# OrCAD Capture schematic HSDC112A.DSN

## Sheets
1 Block Diagram: title: TUSB216I_217A_EVM; rev: A; company: Texas Instruments; note: HSDC112A
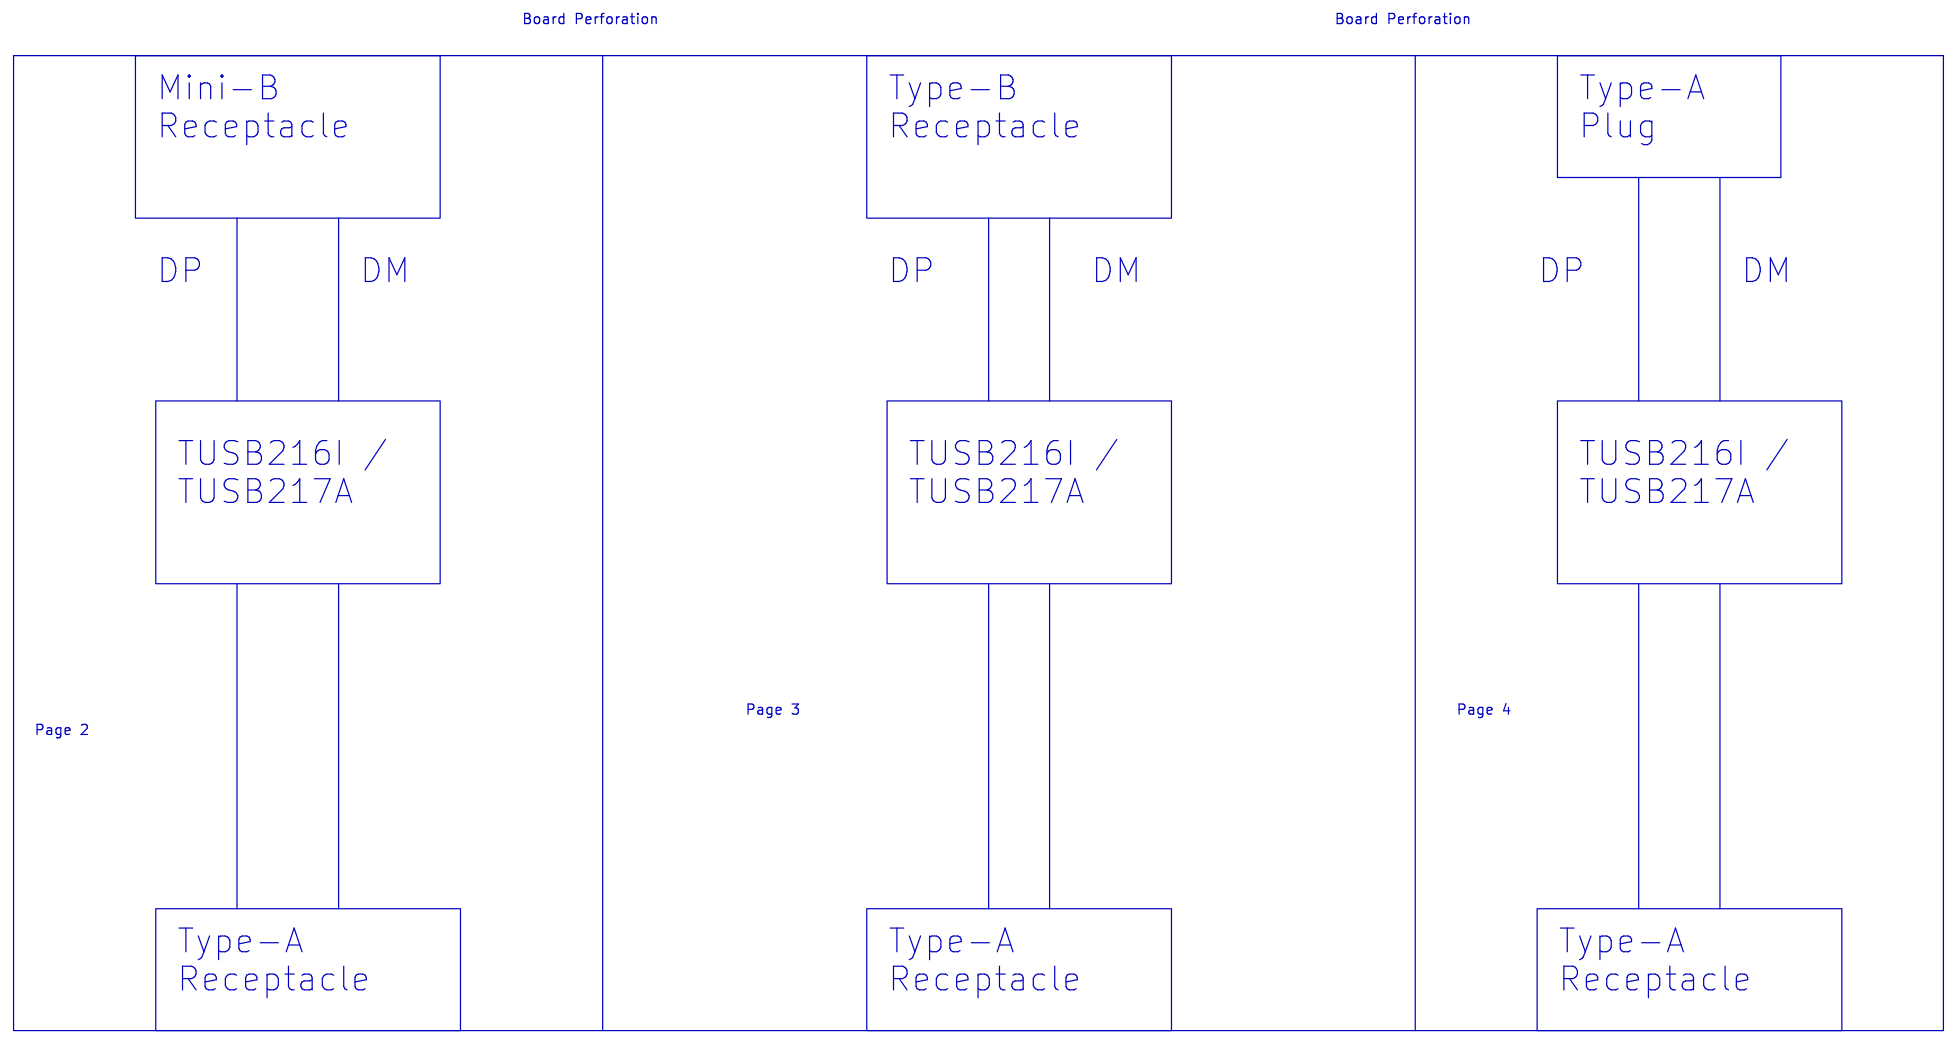
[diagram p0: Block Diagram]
2 Hardware
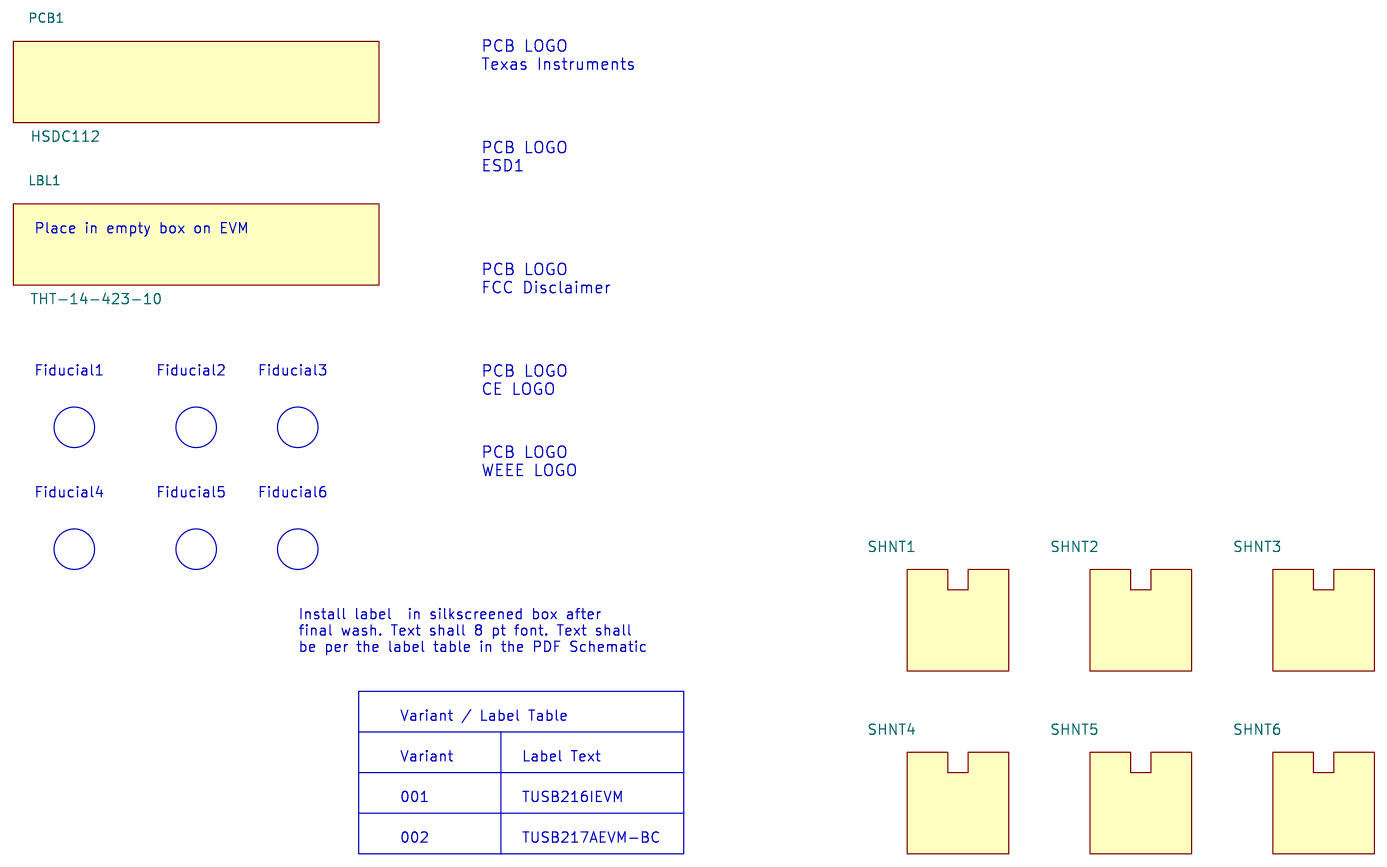
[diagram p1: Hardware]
3 PAGE1: size B
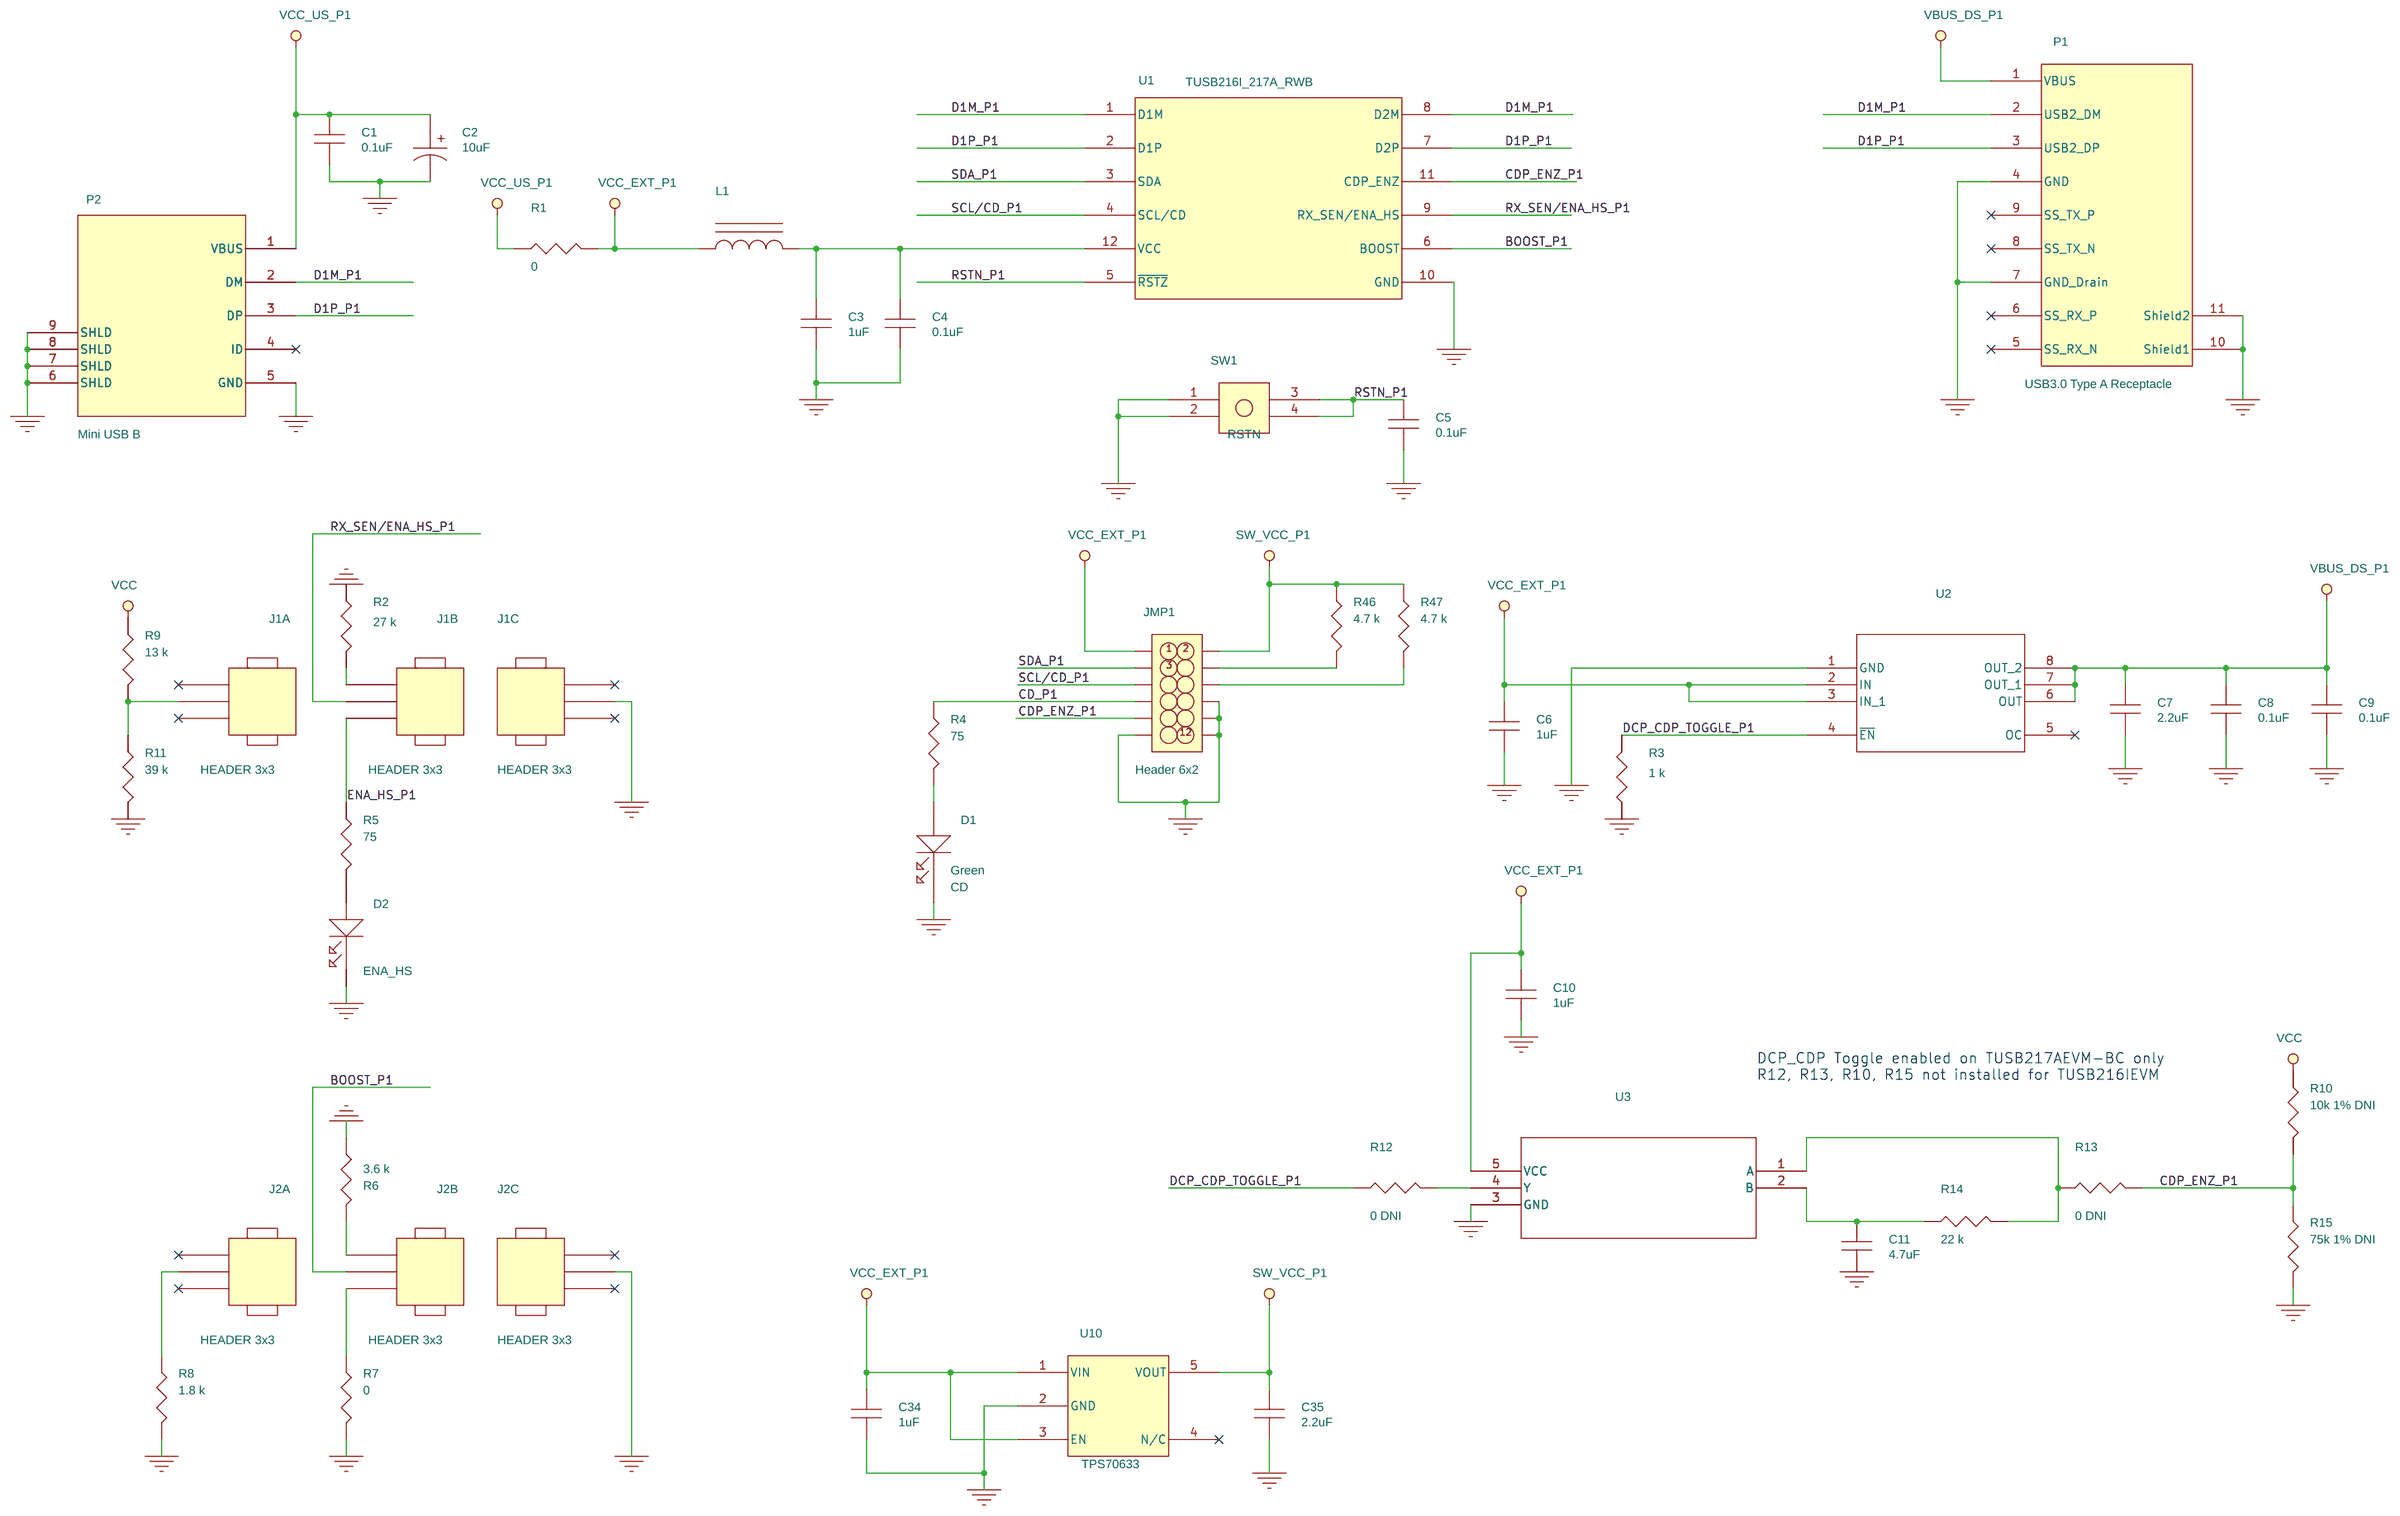
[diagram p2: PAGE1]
4 PAGE2: size B
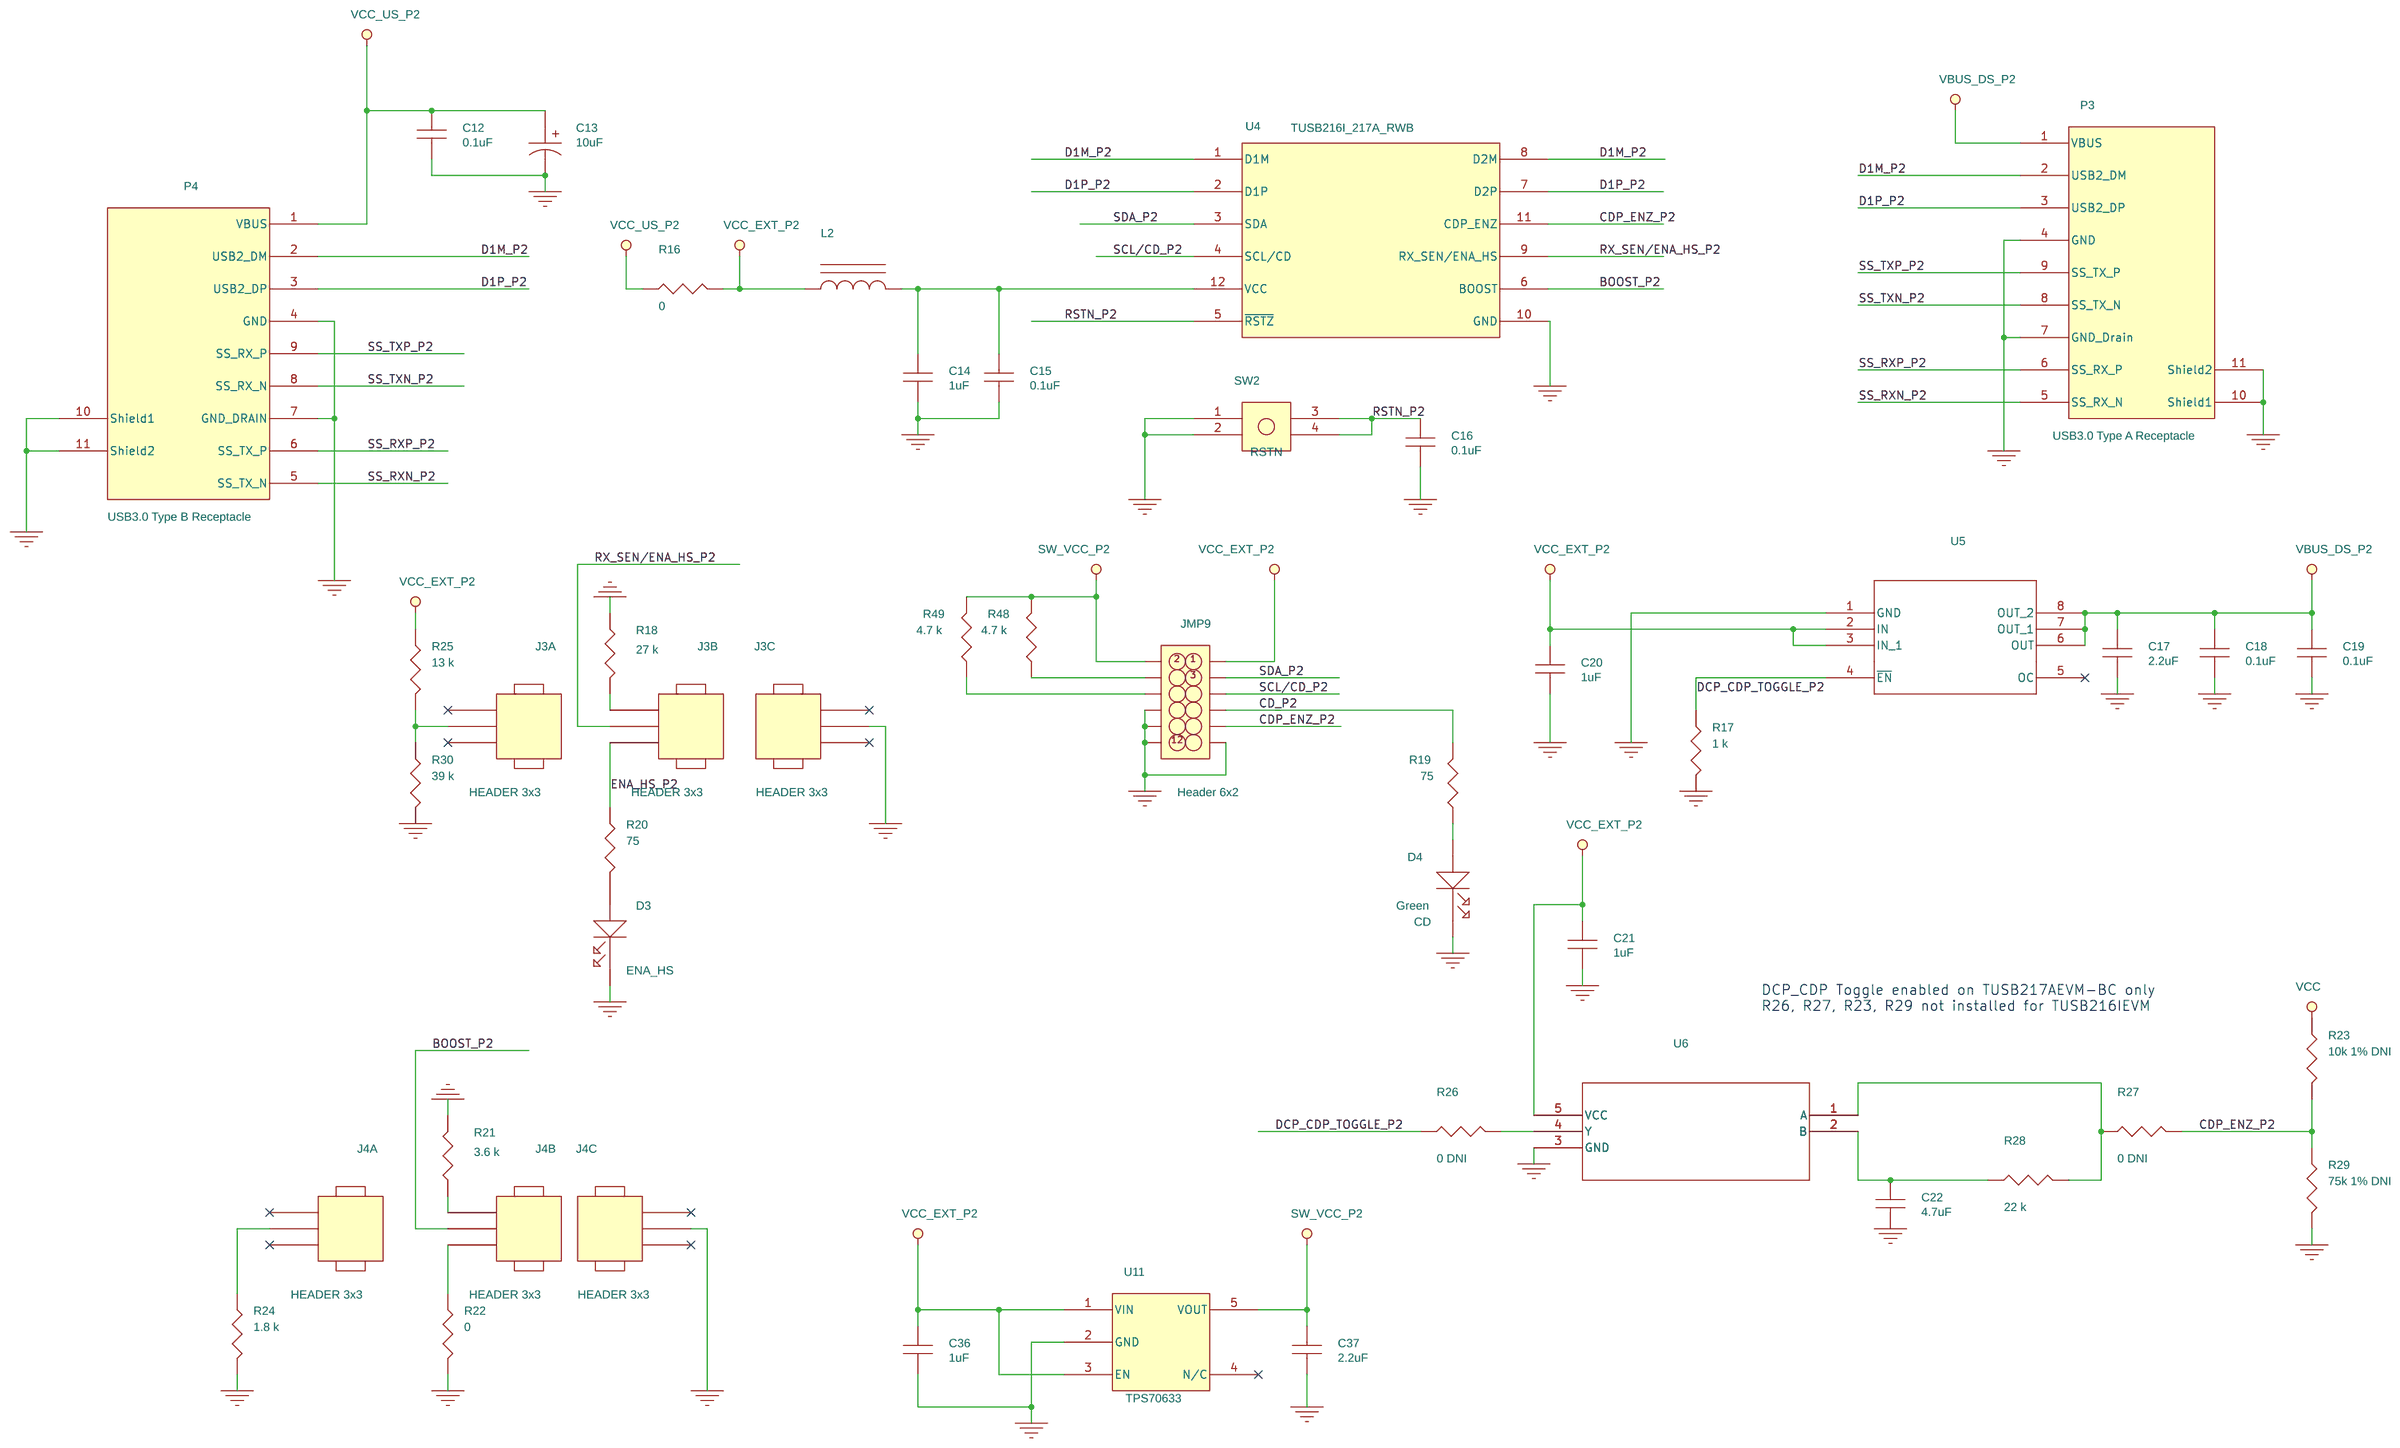
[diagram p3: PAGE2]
5 PAGE3: size B
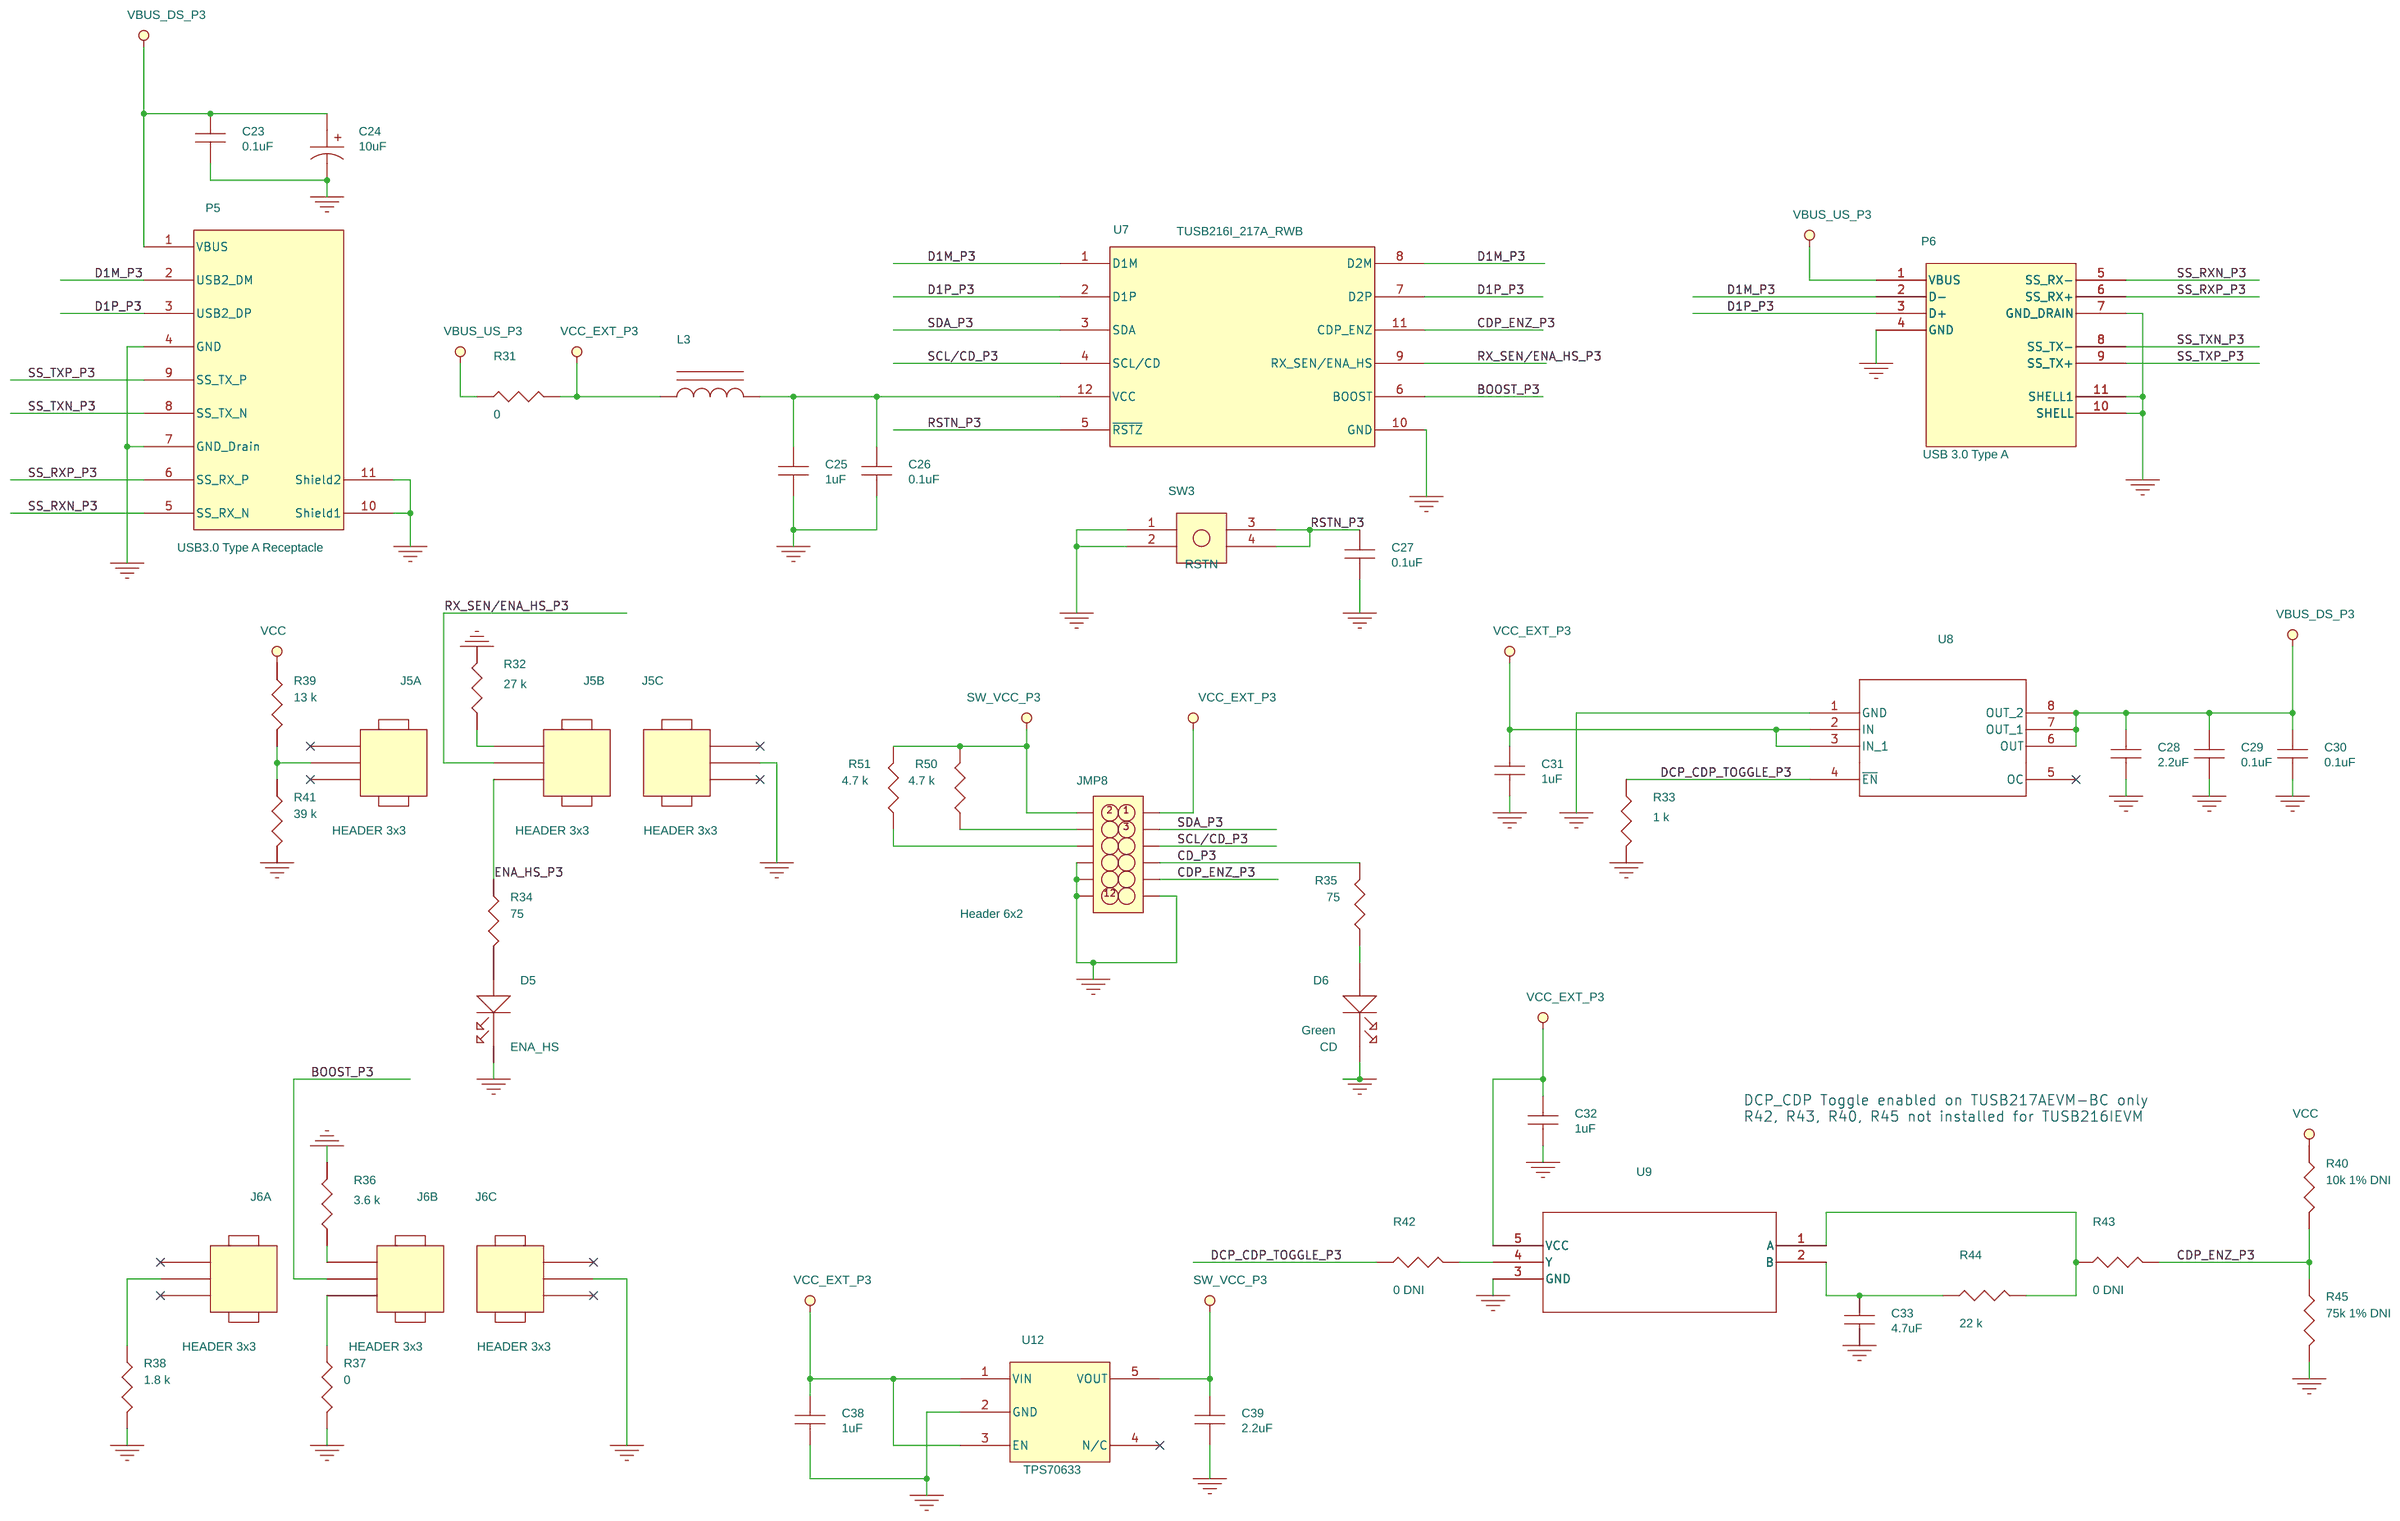
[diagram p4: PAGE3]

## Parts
sheet Hardware
LBL1  THT-14-423-10  [n/a]
PCB1  HSDC112  [n/a]
SHNT1  QPC02SXGN-RC  [.1]
SHNT2  QPC02SXGN-RC  [.1]
SHNT3  QPC02SXGN-RC  [.1]
SHNT4  QPC02SXGN-RC  [.1]
SHNT5  QPC02SXGN-RC  [.1]
SHNT6  QPC02SXGN-RC  [.1]
sheet PAGE1
C1  0.1uF  [cap_0402]
C2  10uF  [cap_0805]
C3  1uF  [cap_0603]
C4  0.1uF  [cap_0402]
C5  0.1uF  [cap_0402]
C6  1uF  [cap_0603]
C7  2.2uF  [cap_0603]
C8  0.1uF  [cap_0402]
C9  0.1uF  [cap_0402]
C10  1uF  [cap_0603]
C11  4.7uF  [cap_0402]
C34  1uF  [cap_0603]
C35  2.2uF  [cap_0603]
D1  LED  [LED_SM_LTST-C171]
D2  LED  [LED_SM_LTST-C171]
J1  HEADER 3x3  (sections A,B,C)
J2  HEADER 3x3  (sections A,B,C)
JMP1  Header 6x2  [HDR_THVT_2X6_200_576]
L1  100ohms  [FB_0603]
P1  USB3.0 Type A Receptacle  [USB-A_THRT_GSB311131HR]
P2  Mini USB B  [USB-mB_SMRT_0548191572]
R1  0  [res_0402]
R2  27 k  [res_0402]
R3  1 k  [res_0402]
R4  75  [res_0402]
R5  75  [res_0402]
R6  3.6 k  [res_0402]
R7  0  [res_0402]
R8  1.8 k  [res_0402]
R9  13 k  [res_0402]
R10  10k 1% DNI  [res_0402]
R11  39 k  [res_0402]
R12  0 DNI  [res_0402]
R13  0 DNI  [res_0402]
R14  22 k  [res_0402]
R15  75k 1% DNI  [res_0402]
R46  4.7 k  [res_0402]
R47  4.7 k  [res_0402]
SW1  Switch - Push Button  [SW_THVT_PTS645SL50-2]
U1  TUSB216I_217A_RWB  [RWB0012AA]
U2  TPS2024D  [D0008AA]
U3  SN74AHC1G86DBV  [DBV0005AA]
U10  TPS70633  [DBV5]
sheet PAGE2
C12  0.1uF  [cap_0402]
C13  10uF  [cap_0805]
C14  1uF  [cap_0603]
C15  0.1uF  [cap_0402]
C16  0.1uF  [cap_0402]
C17  2.2uF  [cap_0603]
C18  0.1uF  [cap_0402]
C19  0.1uF  [cap_0402]
C20  1uF  [cap_0603]
C21  1uF  [cap_0603]
C22  4.7uF  [cap_0402]
C36  1uF  [cap_0603]
C37  2.2uF  [cap_0603]
D3  LED  [LED_SM_LTST-C171]
D4  LED  [LED_SM_LTST-C171]
J3  HEADER 3x3  (sections A,B,C)
J4  HEADER 3x3  (sections A,B,C)
JMP9  Header 6x2  [HDR_THVT_2X6_200_576]
L2  100ohms  [FB_0603]
P3  USB3.0 Type A Receptacle  [USB-A_THRT_GSB311131HR]
P4  USB3.0 Type B Receptacle  [USB-B_THRT_GSB3211311WEU]
R16  0  [res_0402]
R17  1 k  [res_0402]
R18  27 k  [res_0402]
R19  75  [res_0402]
R20  75  [res_0402]
R21  3.6 k  [res_0402]
R22  0  [res_0402]
R23  10k 1% DNI  [res_0402]
R24  1.8 k  [res_0402]
R25  13 k  [res_0402]
R26  0 DNI  [res_0402]
R27  0 DNI  [res_0402]
R28  22 k  [res_0402]
R29  75k 1% DNI  [res_0402]
R30  39 k  [res_0402]
R48  4.7 k  [res_0402]
R49  4.7 k  [res_0402]
SW2  Switch - Push Button  [SW_THVT_PTS645SL50-2]
U4  TUSB216I_217A_RWB  [RWB0012AA]
U5  TPS2024D  [D0008AA]
U6  SN74AHC1G86DBV  [DBV0005AA]
U11  TPS70633  [DBV5]
sheet PAGE3
C23  0.1uF  [cap_0402]
C24  10uF  [cap_0805]
C25  1uF  [cap_0603]
C26  0.1uF  [cap_0402]
C27  0.1uF  [cap_0402]
C28  2.2uF  [cap_0603]
C29  0.1uF  [cap_0402]
C30  0.1uF  [cap_0402]
C31  1uF  [cap_0603]
C32  1uF  [cap_0603]
C33  4.7uF  [cap_0402]
C38  1uF  [cap_0603]
C39  2.2uF  [cap_0603]
D5  LED  [LED_SM_LTST-C171]
D6  LED  [LED_SM_LTST-C171]
J5  HEADER 3x3  (sections A,B,C)
J6  HEADER 3x3  (sections A,B,C)
JMP8  Header 6x2  [HDR_THVT_2X6_200_576]
L3  100ohms  [FB_0603]
P5  USB3.0 Type A Receptacle  [USB-A_THRT_GSB311131HR]
P6  USB 3.0 Type A  [USB-A_SMRT_GSB316441CEU]
R31  0  [res_0402]
R32  27 k  [res_0402]
R33  1 k  [res_0402]
R34  75  [res_0402]
R35  75  [res_0402]
R36  3.6 k  [res_0402]
R37  0  [res_0402]
R38  1.8 k  [res_0402]
R39  13 k  [res_0402]
R40  10k 1% DNI  [res_0402]
R41  39 k  [res_0402]
R42  0 DNI  [res_0402]
R43  0 DNI  [res_0402]
R44  22 k  [res_0402]
R45  75k 1% DNI  [res_0402]
R50  4.7 k  [res_0402]
R51  4.7 k  [res_0402]
SW3  Switch - Push Button  [SW_THVT_PTS645SL50-2]
U7  TUSB216I_217A_RWB  [RWB0012AA]
U8  TPS2024D  [D0008AA]
U9  SN74AHC1G86DBV  [DBV0005AA]
U12  TPS70633  [DBV5]

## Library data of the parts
LBL1 = PCB: Manufacturer: Brady
PCB1 = PCB: Manufacturer: Any
SHNT1-SHNT6 = Shunt: Digikey: S9337-ND; Manufacturer: Sullins
C1 C4 C5 C8 C9 C12 C15 C16 C18 C19 C23 C26 C27 C29 C30 = cc0402: Digikey: 311-1336-1-ND; Manufacturer: Yageo; Manufacturer Part Number: CC0402KRX5R6BB104
C2 C13 C24 = CAPACITOR_POL: Digikey: 399-4925-1-ND; Manufacturer: Kemet; Manufacturer Part Number: C0805C106K8PACTU
C3 C6 C10 C14 C20 C21 C25 C31 C32 C34 C36 C38 = cc0603: Digikey: 587-1242-1-ND; Manufacturer: Taiyo Yuden; Manufacturer Part Number: LMK107B7105KA-T
C7 C17 C28 C35 C37 C39 = cc0603: Digikey: 587-4901-1-ND; Manufacturer: Taiyo Yuden; Manufacturer Part Number: JMK107B7225MA-TR
C11 C22 C33 = cc0402: Digikey: 311-3477-1-ND; Manufacturer: Yageo; Manufacturer Part Number: CC0402KRX5R6BB475
D1 D4 D6 = d0805_Blue: Comp_Des: Green; Digikey: 160-1423-1-ND; Manufacturer Part Number: LTST-C171GKT; SILKTEXT1: CD; Vf: 2.1V
D2 D3 D5 = d0805_Green: Digikey: 160-1423-1-ND; Manufacturer Part Number: LTST-C171GKT; SILKTEXT1: ENA_HS; Vf: 2.1V
J1-J6 = HEADER_3x3: Digikey: SAM15360-ND; Manufacturer: Samtec; Manufacturer Part Number: TSW-103-07-L-T
JMP1 JMP9 = Header_6x2: Digikey: 609-3237-ND; Manufacturer: Amphenol ICC (FCI); Manufacturer Part Number: 67997-212HLF
L1-L3 = Ferrite_Bead_500ohm: Digikey: 445-2984-1-ND; Imax: 2A; Manufacturer: TDK Corporation; Manufacturer Part Number: MPZ1608Y101BTA00
P1 P3 P5 = USB_3.0_Type_A_Receptacle: Digikey: GSB311131HR-ND; Manufacturer: Amphenol; Manufacturer Part Number: GSB311131HR
P2 = Mini_USB_B_3: Digikey: WM6794CT-ND; Manufacturer: Molex; Manufacturer Part Number: 0548191572
R1 R7 R12 R13 R16 R22 R26 R27 R31 R37 R42 R43 = r0402: Digikey: YAG1279CT-ND; Manufacturer: Yageo; Manufacturer Part Number: RC0402JR-070RP
R2 R18 R32 = r0402: Digikey: 311-27KJRCT-ND; Manufacturer: Yageo; Manufacturer Part Number: RC0402JR-0727KL
R3 R17 R33 = r0402: Digikey: YAG1284CT-ND; Manufacturer: Yageo; Manufacturer Part Number: RC0402JR-071KP
R4 R5 R19 R20 R34 R35 = r0402: Digikey: 311-75JRCT-ND; Manufacturer: Yageo; Manufacturer Part Number: RC0402JR-0775RL
R6 R21 R36 = r0402: Digikey: 311-3.6KJRCT-ND; Manufacturer: Yageo; Manufacturer Part Number: RC0402JR-073K6L
R8 R24 R38 = r0402: Digikey: 311-1.8KJRCT-ND; Manufacturer: Yageo; Manufacturer Part Number: RC0402JR-071K8L
R9 R25 R39 = r0402: Digikey: YAG3274CT-ND; Manufacturer: Yageo; Manufacturer Part Number: RC0402JR-0713KL
R10 R23 R40 = r0402: Digikey: 13-RE0402FRE0710KLCT-ND; Manufacturer: Yageo; Manufacturer Part Number: RE0402FRE0710KL
R11 R30 R41 = r0402: Digikey: 311-39KJRCT-ND; Manufacturer: Yageo; Manufacturer Part Number: RC0402JR-0739KL
R14 R28 R44 = r0402: Digikey: 311-22KJRCT-ND; Manufacturer: Yageo; Manufacturer Part Number: RC0402JR-0722KL
R15 R29 R45 = r0402: Digikey: 13-RT0402FRE0775KLCT-ND; Manufacturer: Yageo; Manufacturer Part Number: RT0402FRE0775KL
R46-R51 = r0402: Digikey: 311-4.7KJRCT-ND; Manufacturer: Yageo; Manufacturer Part Number: RC0402JR-074K7L
SW1-SW3 = Switch_-_Push_Button_0: Digikey: 450-1650-ND; Manufacturer: C&K; Manufacturer Part Number: PTS645SL50-2 LFS; SILKTEXT1: RSTN
U1 U4 U7 = TUSB216RWB_2: Manufacturer: Texas Instruments; Manufacturer Part Number: TUSB21XXRWB; PACKAGE_DESIGNATOR: RWB; Vendor: Texas Instruments
U2 U5 U8 = TPS2024_D_1
U3 U6 U9 = SN74AHC1G86_DBV
U10-U12 = TPS706: Digikey: 296-41975-2-ND; Manufacturer: Texas Instruments; Manufacturer Part Number: TPS70633DBV
P4 = USB_3.0_Type_B_Receptacle: Digikey: GSB3211311WEU-ND; Manufacturer: Amphenol; Manufacturer Part Number: GSB3211311WEU
JMP8 = Header_6x2: Comp_Des: Amphenol ICC (FCI); Digikey: 609-3237-ND; Manufacturer: Amphenol ICC (FCI); Manufacturer Part Number: 67997-212HLF
P6 = USB_3_1.0_Type_A: Digikey: GSB316441CEUCT-ND; Manufacturer: Amphenol ICC (Commercial Products); Manufacturer Part Number: GSB316441CEU

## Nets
GND: C1.2 C2.2 C3.2 C4.2 C5.2 C6.2 C7.2 C8.2 C9.2 C10.2 C11.2 C12.2 C13.2 C14.2 C15.2 C16.2 C17.2 C18.2 C19.2 C20.2 C21.2 C22.2 C23.2 C24.2 C25.2 C26.2 C27.2 C28.2 C29.2 C30.2 C31.2 C32.2 C33.2 C34.2 C35.2 C36.2 C37.2 C38.2 C39.2 D1.1 D2.1 D3.1 D4.1 D5.1 D6.1 J1.6 J2.6 J3.6 J4.6 J5.6 J6.6 JMP1.8 JMP1.10 JMP1.11 JMP1.12 JMP8.8 JMP8.10 JMP8.11 JMP8.12 JMP9.8 JMP9.10 JMP9.11 JMP9.12 P1.4(GND) P1.7(GND_Drain) P1.10(Shield1) P1.11(Shield2) P2.5(GND) P2.6(SHLD) P2.7(SHLD) P2.8(SHLD) P2.9(SHLD) P3.4(GND) P3.7(GND_Drain) P3.10(Shield1) P3.11(Shield2) P4.4(GND) P4.7(GND_DRAIN) P4.10(Shield1) P4.11(Shield2) P5.4(GND) P5.7(GND_Drain) P5.10(Shield1) P5.11(Shield2) P6.4(GND) P6.7(GND_DRAIN) P6.10(SHELL) P6.11(SHELL1) R2.1 R3.1 R6.2 R7.2 R8.2 R11.2 R15.2 R17.2 R18.2 R21.2 R22.2 R24.2 R29.2 R30.2 R32.1 R33.2 R36.2 R37.2 R38.2 R41.2 R45.2 SW1.1 SW1.2 SW2.1 SW2.2 SW3.1 SW3.2 U1.10(GND) U2.1(GND) U3.3(GND) U4.10(GND) U5.1(GND) U6.3(GND) U7.10(GND) U8.1(GND) U9.3(GND) U10.2(GND) U11.2(GND) U12.2(GND)
VBUS_DS_P1: C7.1 C8.1 C9.1 P1.1(VBUS) U2.6(OUT) U2.7(OUT_1) U2.8(OUT_2)
VBUS_DS_P2: C17.1 C18.1 C19.1 P3.1(VBUS) U5.6(OUT) U5.7(OUT_1) U5.8(OUT_2)
VBUS_DS_P3: C23.1 C24.1 C28.1 C29.1 C30.1 P5.1(VBUS) U8.6(OUT) U8.7(OUT_1) U8.8(OUT_2)
VBUS_US_P3: P6.1(VBUS) R31.1 R40.1
VCC_EXT_P1: C6.1 C10.1 C34.1 JMP1.1 L1.1 R1.2 R9.1 U2.2(IN) U2.3(IN_1) U3.5(VCC) U10.1(VIN) U10.3(EN)
VCC_EXT_P2: C20.1 C21.1 C36.1 JMP9.1 L2.1 R16.2 R25.1 U5.2(IN) U5.3(IN_1) U6.5(VCC) U11.1(VIN) U11.3(EN)
VCC_EXT_P3: C31.1 C32.1 C38.1 JMP8.1 L3.1 R31.2 R39.1 U8.2(IN) U8.3(IN_1) U9.5(VCC) U12.1(VIN) U12.3(EN)
VCC_US_P1: C1.1 C2.1 P2.1(VBUS) R1.1 R10.1
VCC_US_P2: C12.1 C13.1 P4.1(VBUS) R16.1 R23.1
BOOST_P1: J2.5 U1.6(BOOST)
BOOST_P2: J4.5 U4.6(BOOST)
BOOST_P3: J6.5 U7.6(BOOST)
CD_P1: JMP1.7 R4.1
CD_P2: JMP9.7 R19.1
CD_P3: JMP8.7 R35.1
CDP_ENZ_P1: JMP1.9 R10.2 R13.2 R15.1 U1.11(CDP_ENZ)
CDP_ENZ_P2: JMP9.9 R23.2 R27.2 R29.1 U4.11(CDP_ENZ)
CDP_ENZ_P3: JMP8.9 R40.2 R43.2 R45.1 U7.11(CDP_ENZ)
D1M_P1: P1.2(USB2_DM) P2.2(DM) U1.1(D1M) U1.8(D2M)
D1M_P2: P3.2(USB2_DM) P4.2(USB2_DM) U4.1(D1M) U4.8(D2M)
D1M_P3: P5.2(USB2_DM) P6.2(D-) U7.1(D1M) U7.8(D2M)
D1P_P1: P1.3(USB2_DP) P2.3(DP) U1.2(D1P) U1.7(D2P)
D1P_P2: P3.3(USB2_DP) P4.3(USB2_DP) U4.2(D1P) U4.7(D2P)
D1P_P3: P5.3(USB2_DP) P6.3(D+) U7.2(D1P) U7.7(D2P)
DCP_CDP_TOGGLE_P1: R3.2 R12.1 U2.4(~{EN})
DCP_CDP_TOGGLE_P2: R17.1 R26.1 U5.4(~{EN})
DCP_CDP_TOGGLE_P3: R33.1 R42.1 U8.4(~{EN})
ENA_HS_P1: J1.8 R5.1
ENA_HS_P2: J3.8 R20.1
ENA_HS_P3: J5.8 R34.1
RSTN_P1: C5.1 SW1.3 SW1.4 U1.5(~{RSTZ})
RSTN_P2: C16.1 SW2.3 SW2.4 U4.5(~{RSTZ})
RSTN_P3: C27.1 SW3.3 SW3.4 U7.5(~{RSTZ})
RX_SEN/ENA_HS_P1: J1.5 U1.9(RX_SEN/ENA_HS)
RX_SEN/ENA_HS_P2: J3.5 U4.9(RX_SEN/ENA_HS)
RX_SEN/ENA_HS_P3: J5.5 U7.9(RX_SEN/ENA_HS)
SCL/CD_P1: JMP1.5 U1.4(SCL/CD)
SCL/CD_P2: JMP9.5 U4.4(SCL/CD)
SCL/CD_P3: JMP8.5 U7.4(SCL/CD)
SDA_P1: JMP1.3 U1.3(SDA)
SDA_P2: JMP9.3 U4.3(SDA)
SDA_P3: JMP8.3 U7.3(SDA)
SS_RXN_P2: P3.5(SS_RX_N) P4.5(SS_TX_N)
SS_RXN_P3: P5.5(SS_RX_N) P6.5(SS_RX-)
SS_RXP_P2: P3.6(SS_RX_P) P4.6(SS_TX_P)
SS_RXP_P3: P5.6(SS_RX_P) P6.6(SS_RX+)
SS_TXN_P2: P3.8(SS_TX_N) P4.8(SS_RX_N)
SS_TXN_P3: P5.8(SS_TX_N) P6.8(SS_TX-)
SS_TXP_P2: P3.9(SS_TX_P) P4.9(SS_RX_P)
SS_TXP_P3: P5.9(SS_TX_P) P6.9(SS_TX+)
SW_VCC_P1: C35.1 JMP1.2 R46.1 R47.1 U10.5(VOUT)
SW_VCC_P2: C37.1 JMP9.2 R48.1 R49.1 U11.5(VOUT)
SW_VCC_P3: C39.1 JMP8.2 R50.1 R51.1 U12.5(VOUT)
N16790170: R27.1 R28.2 U6.1(A)
N16790175: C22.1 R28.1 U6.2(B)
N16793543: R26.2 U6.4(Y)
N16795852: R43.1 R44.2 U9.1(A)
N16795856: C33.1 R44.1 U9.2(B)
N16796357: R42.2 U9.4(Y)
N16796414: D6.2 R35.2
N16797569: R13.1 R14.2 U3.1(A)
N16798025: C3.1 C4.1 L1.2 U1.12(VCC)
N16798074: R12.2 U3.4(Y)
N16798131: D1.2 R4.2
N16810380: J1.4 R9.2 R11.1
N16810407: J2.8 R7.1
N16810514: J2.2 R6.1
N16813878: C14.1 C15.1 L2.2 U4.12(VCC)
N16814597: C25.1 C26.1 L3.2 U7.12(VCC)
N16860679: J3.4 R25.2 R30.1
N16860703: J4.8 R22.1
N16860789: J4.2 R21.1
N16861643: J5.4 R39.2 R41.1
N16861663: J6.4 R38.1
N16861667: J6.8 R37.1
N16861753: J6.2 R36.1
N16876268: C11.1 R14.1 U3.2(B)
N16883773: D4.2 R19.2
N16915178: JMP1.4 R46.2
N16915181: JMP1.6 R47.2
N16916526: JMP9.6 R49.2
N16916965: JMP9.4 R48.2
N16917043: JMP8.6 R51.2
N16917272: JMP8.4 R50.2
N16929690: J1.2 R2.2
N16931613: J2.4 R8.1
N16933252: J3.2 R18.1
N16935144: J4.4 R24.1
N16936334: J5.2 R32.2
N16943079: D2.2 R5.2
N16943426: D3.2 R20.2
N16945489: D5.2 R34.2

Not connected (* = marked no-connect by the designer): J1 1* 3* 7* 9*; J2 1* 3* 7* 9*; J3 1* 3* 7* 9*; J4 1* 3* 7* 9*; J5 1* 3* 7* 9*; J6 1* 3* 7* 9*; P1 5(SS_RX_N)* 6(SS_RX_P)* 8(SS_TX_N)* 9(SS_TX_P)*; P2 4(ID)*; U2 5(OC)*; U5 5(OC)*; U8 5(OC)*; U10 4(N/C)*; U11 4(N/C)*; U12 4(N/C)*

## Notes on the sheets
sheet 1
- Board Perforation
- Board Perforation
- Mini-B
  Receptacle
- Type-B
  Receptacle
- Type-A
  Plug
- DP
- DM
- DP
- DM
- DP
- DM
- TUSB216I /
  TUSB217A
- TUSB216I /
  TUSB217A
- TUSB216I /
  TUSB217A
- Page 3
- Page 4
- Page 2
- Type-A
  Receptacle
- Type-A
  Receptacle
- Type-A
  Receptacle
sheet 2
- PCB LOGO
  Texas Instruments
- PCB LOGO
  ESD1
- Place in empty box on EVM
- PCB LOGO
  FCC Disclaimer
- Fiducial1
- Fiducial2
- Fiducial3
- PCB LOGO
  CE LOGO
- PCB LOGO
  WEEE LOGO
- Fiducial4
- Fiducial5
- Fiducial6
- Install label  in silkscreened box after
  final wash. Text shall 8 pt font. Text shall
  be per the label table in the PDF Schematic
- Variant / Label Table
- Variant
- Label Text
- 001
- TUSB216IEVM
- 002
- TUSB217AEVM-BC
sheet 3
- DCP_CDP Toggle enabled on TUSB217AEVM-BC only
  R12, R13, R10, R15 not installed for TUSB216IEVM
sheet 4
- DCP_CDP Toggle enabled on TUSB217AEVM-BC only
  R26, R27, R23, R29 not installed for TUSB216IEVM
sheet 5
- DCP_CDP Toggle enabled on TUSB217AEVM-BC only
  R42, R43, R40, R45 not installed for TUSB216IEVM
